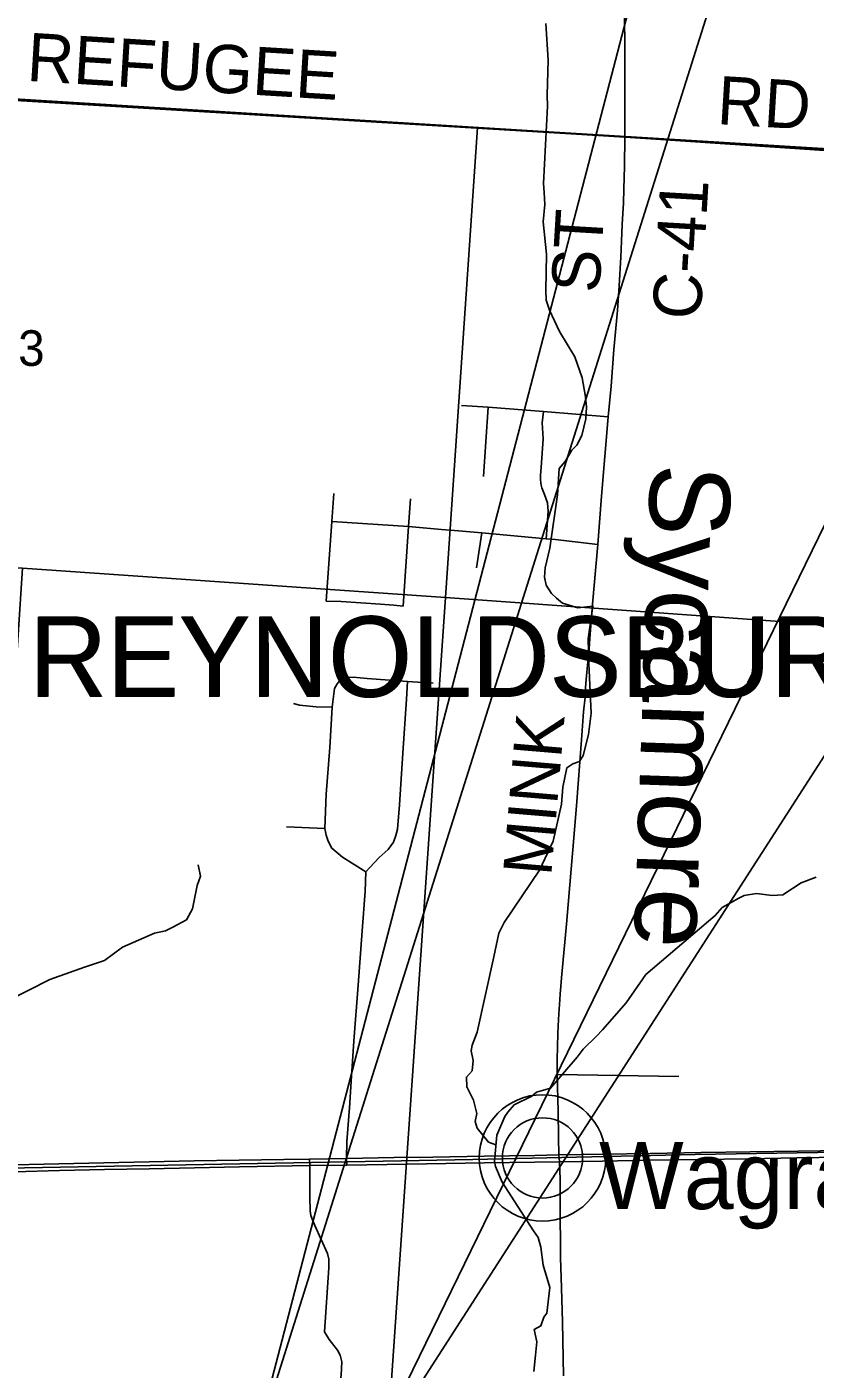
# Model space of a CAD drawing. Extents: x 0 to 34, y 0 to 22.
# Drawn here: x 2.718 to 3.646, y 16.964 to 18.544 of the extents above; entities that cross this region are included whole.
import ezdxf

# ---------------------------------------------------------------- set-up
doc = ezdxf.new("R2010")
doc.units = 0
for name, color, linetype in [('GM_X_City_Street', 7, 'Continuous'), ('GM_X_Corporation', 7, 'Continuous'), ('GM_X_Corporation_Text', 7, 'Continuous'), ('GM_X_County_Road', 7, 'Continuous'), ('GM_X_County_Road_Text', 7, 'Continuous'), ('GM_X_Minor_River', 7, 'Continuous'), ('GM_X_Minor_River_Text', 7, 'Continuous'), ('GM_X_Rail_Line', 7, 'Continuous'), ('GM_X_Section', 7, 'Continuous'), ('GM_X_Section_Text', 7, 'Continuous'), ('GM_X_Township_Road', 7, 'Continuous'), ('GM_X_Township_Road_Text', 7, 'Continuous'), ('GM_X_Unincorporated', 7, 'Continuous'), ('GM_X_Unincorporated_Location', 7, 'Continuous'), ('GM_X_Unincorporated_Text', 7, 'Continuous'), ('GM_X_US_Route', 7, 'Continuous'), ('SH_Text', 7, 'Continuous')]:
    doc.layers.add(name, color=color, linetype=linetype)

msp = doc.modelspace()

# ---------------------------------------------------------------- linework, layer by layer
at = {"layer": 'GM_X_City_Street'}
msp.add_lwpolyline([(8.3697, 20.9), (2.1, 20.9), (2.1, 18.8151), (2.1233, 18.8137), (2.129, 18.8133), (2.1078, 18.4924), (2.1111, 18.4924), (2.2415, 18.4869), (2.2482, 18.4853), (3.4177, 18.4149), (4.6284, 18.3336)], dxfattribs=at)
at = {"layer": 'GM_X_Corporation'}
for points in [[(6.4385, 20.9), (2.1, 20.9), (2.1, 18.4929), (2.1111, 18.4924), (2.2415, 18.4869), (2.5696, 18.468), (3.4218, 18.4152), (4.6285, 18.3373)], [(4.6285, 18.3373), (3.4218, 18.4152), (2.5696, 18.468), (2.2415, 18.4869), (2.1111, 18.4924), (2.1, 18.4929), (2.1, 15.9442), (2.2903, 15.9292), (2.5827, 15.9132), (2.6921, 15.9056), (2.7799, 15.8989), (2.8362, 15.8952), (3.3132, 15.8609), (3.9945, 15.8088)]]:
    msp.add_lwpolyline(points, dxfattribs=at)
at = {"layer": 'GM_X_County_Road'}
for points in [[(3.4075, 19.409), (3.4081, 19.3816), (3.409, 19.3382), (3.4098, 19.2932), (3.4107, 19.2269), (3.4112, 19.2096), (3.4118, 19.1857), (3.4122, 19.138), (3.413, 19.0859), (3.4136, 19.0691), (3.4144, 19.0397), (3.4155, 18.9809), (3.4164, 18.9378), (3.4171, 18.8919), (3.4175, 18.8583), (3.4184, 18.8084), (3.4193, 18.743), (3.4205, 18.6587), (3.421, 18.613), (3.4215, 18.5781), (3.4224, 18.5261), (3.4223, 18.4686), (3.4221, 18.4146)], [(3.4221, 18.4146), (3.4218, 18.3802), (3.4209, 18.3532), (3.4205, 18.3371), (3.4191, 18.3117), (3.4184, 18.2921), (3.4175, 18.2734), (3.4156, 18.2396), (3.4136, 18.2104), (3.4095, 18.1646), (3.4062, 18.1213), (3.4027, 18.0854), (3.3949, 17.9919), (3.3904, 17.935), (3.3844, 17.8647), (3.381, 17.8244), (3.3797, 17.8067), (3.3784, 17.7929), (3.3773, 17.7805), (3.376, 17.7666), (3.3754, 17.7553), (3.3738, 17.7381), (3.3713, 17.705), (3.3693, 17.6792), (3.3675, 17.6534), (3.3659, 17.6326), (3.3622, 17.5898), (3.3575, 17.5344), (3.3535, 17.4882), (3.3478, 17.4248), (3.3469, 17.4148), (3.3463, 17.4059), (3.3457, 17.3989), (3.3446, 17.3826), (3.3438, 17.3685), (3.3434, 17.3589), (3.343, 17.344), (3.3428, 17.3284), (3.3428, 17.3185), (3.3428, 17.3112), (3.3437, 17.2678), (3.344, 17.2369), (3.3446, 17.2166), (3.3453, 17.2083)], [(3.3453, 17.2083), (3.3463, 17.1876), (3.3461, 17.1598), (3.3465, 17.0957), (3.3479, 17.0598), (3.349, 17.0196), (3.3501, 16.9565)]]:
    msp.add_lwpolyline(points, dxfattribs=at)
at = {"layer": 'GM_X_Minor_River'}
for points in [[(3.2706, 17.2284), (3.2619, 17.2313), (3.2483, 17.248), (3.246, 17.2556), (3.2479, 17.2651), (3.2442, 17.2807), (3.2363, 17.2966), (3.2359, 17.308), (3.2424, 17.3156), (3.2439, 17.3274), (3.2413, 17.3388), (3.2424, 17.3456), (3.2485, 17.3611), (3.268, 17.4495), (3.2741, 17.4776), (3.2802, 17.4901), (3.322, 17.5515), (3.3349, 17.5792), (3.338, 17.5856), (3.3479, 17.6293), (3.3491, 17.6494), (3.354, 17.6722), (3.3612, 17.6767), (3.3688, 17.6797), (3.3734, 17.6865), (3.3795, 17.7112), (3.3826, 17.7366), (3.38, 17.7951), (3.3793, 17.8239), (3.3847, 17.8626), (3.3669, 17.8604), (3.3488, 17.8661), (3.3419, 17.8718), (3.3359, 17.8772), (3.3295, 17.887), (3.3276, 17.8965), (3.3284, 17.9075), (3.3341, 17.9307), (3.343, 17.9933), (3.3449, 18.0244), (3.3521, 18.0327), (3.3597, 18.046), (3.3658, 18.0521), (3.3715, 18.0634), (3.3765, 18.0828), (3.3772, 18.0965), (3.3761, 18.109), (3.3743, 18.1177), (3.372, 18.1314), (3.3634, 18.1561), (3.3452, 18.1857), (3.3335, 18.2108), (3.3298, 18.2226), (3.3291, 18.234), (3.3299, 18.2769), (3.3262, 18.3148), (3.3281, 18.3353), (3.3274, 18.3494), (3.3267, 18.36), (3.3314, 18.4511), (3.331, 18.464), (3.3319, 18.5053), (3.3293, 18.5482)], [(2.6703, 17.3848), (2.7454, 17.423), (2.7863, 17.4373), (2.8098, 17.4452), (2.831, 17.4608), (2.8686, 17.4774), (2.8818, 17.4804), (2.8902, 17.4845), (2.9065, 17.4932), (2.9133, 17.5061), (2.919, 17.5334), (2.9228, 17.5444), (2.9202, 17.5581)], [(3.3151, 16.9616), (3.317, 16.9806), (3.3186, 16.9962), (3.3156, 17.011), (3.3235, 17.0152), (3.327, 17.0254), (3.3304, 17.0303), (3.3339, 17.0603), (3.326, 17.0865), (3.3234, 17.1078), (3.3204, 17.1192), (3.3147, 17.1272), (3.2777, 17.1842), (3.2702, 17.2028), (3.2687, 17.2089), (3.2717, 17.2396), (3.2809, 17.2616), (3.2847, 17.2669), (3.2919, 17.2753), (3.3127, 17.2855), (3.3184, 17.2904), (3.3347, 17.2949), (3.3662, 17.3313), (3.3731, 17.3411), (3.389, 17.3563), (3.3958, 17.3635), (3.4239, 17.3953), (3.4471, 17.429), (3.5286, 17.4983), (3.537, 17.5078), (3.5563, 17.5187), (3.5628, 17.5218), (3.5772, 17.524), (3.5957, 17.5217), (3.6082, 17.5224), (3.6298, 17.5368), (3.6473, 17.5432)]]:
    msp.add_lwpolyline(points, dxfattribs=at)
at = {"layer": 'GM_X_Rail_Line'}
msp.add_lwpolyline([(2.1, 17.1885), (2.293, 17.1932), (3.2433, 17.211), (3.5049, 17.2168), (5.1641, 17.2441), (5.3961, 17.2441), (6.3843, 17.2591), (6.7484, 17.272), (7.243, 17.2836), (8.0477, 17.3015), (8.4974, 17.3184), (8.9, 17.3324)], dxfattribs=at)
at = {"layer": 'GM_X_Section'}
for points in [[(2.2377, 18.4824), (2.6283, 18.4625), (3.1458, 18.432), (3.2487, 18.4259), (3.2112, 17.8728), (2.7132, 17.9071), (2.1995, 17.9442)], [(3.2487, 18.4259), (3.6748, 18.4), (4.2612, 18.3613), (4.2214, 17.7996), (3.7302, 17.8352), (3.2112, 17.8728)], [(2.7132, 17.9071), (3.2112, 17.8728), (3.1425, 16.8774), (2.648, 16.9108)], [(3.2112, 17.8728), (3.7302, 17.8352), (3.6598, 16.8406), (3.1425, 16.8774)]]:
    msp.add_lwpolyline(points, close=True, dxfattribs=at)
at = {"layer": 'GM_X_Township_Road'}
for p, q in [((3.2561, 18.0152), (3.2613, 18.0968)), ((3.2478, 17.9075), (3.254, 17.9489)), ((3.0242, 17.6025), (3.069, 17.6005)), ((3.3428, 17.3112), (3.4857, 17.3088))]:
    msp.add_line(p, q, dxfattribs=at)
for points in [[(3.4221, 18.4146), (2.5698, 18.4675), (2.2417, 18.4863)], [(5.2116, 18.2984), (4.6288, 18.3368), (3.4221, 18.4146)], [(3.23, 18.0985), (3.2613, 18.0968), (3.3265, 18.0916), (3.4027, 18.0854)], [(3.3297, 17.9416), (3.3321, 17.9741), (3.3312, 17.984), (3.3277, 17.994), (3.3247, 18.0016), (3.3237, 18.0048), (3.3233, 18.0076), (3.3229, 18.0116), (3.323, 18.0167), (3.3237, 18.0255), (3.326, 18.0594), (3.3248, 18.0781), (3.3265, 18.0916)], [(3.0707, 17.8683), (3.0774, 17.9621), (3.0798, 17.9951)], [(3.1615, 17.8624), (3.1678, 17.9561), (3.17, 17.9888)], [(3.0774, 17.9621), (3.1678, 17.9561), (3.2064, 17.9526), (3.2219, 17.9514)], [(3.2219, 17.9514), (3.2263, 17.9511), (3.254, 17.9489), (3.3297, 17.9416), (3.3401, 17.9409), (3.3904, 17.935)], [(3.0707, 17.8683), (3.0882, 17.8679), (3.1346, 17.8646), (3.1502, 17.8635), (3.1615, 17.8624)], [(3.1173, 17.5497), (3.0898, 17.5668), (3.0776, 17.5774), (3.0729, 17.5859), (3.0706, 17.5929), (3.069, 17.6005), (3.0709, 17.6411), (3.0749, 17.696), (3.0779, 17.7435), (3.0806, 17.7656), (3.0835, 17.7711), (3.0878, 17.7756), (3.093, 17.778), (3.1024, 17.7788), (3.119, 17.7772)], [(3.119, 17.7772), (3.1664, 17.7738), (3.1966, 17.7716)], [(3.0949, 17.2044), (3.0947, 17.2123), (3.0952, 17.2322), (3.0982, 17.272), (3.1007, 17.3091), (3.1034, 17.3502), (3.1084, 17.4163), (3.1131, 17.4801), (3.1165, 17.5266), (3.1173, 17.5497), (3.1222, 17.5548), (3.1331, 17.5665), (3.1436, 17.5761), (3.1499, 17.5847), (3.1528, 17.5923), (3.1547, 17.6), (3.1569, 17.6287), (3.1611, 17.6894), (3.1654, 17.753), (3.1664, 17.7738)], [(3.0323, 17.7478), (3.0394, 17.746), (3.0588, 17.7439), (3.0779, 17.7435)], [(3.0513, 17.2116), (3.0514, 17.2038), (3.0516, 17.1668), (3.052, 17.1507), (3.0528, 17.1452), (3.0546, 17.14), (3.0575, 17.1333), (3.0725, 17.1005), (3.074, 17.0936), (3.0738, 17.0835), (3.0687, 17.008), (3.0744, 16.9992)], [(3.0855, 16.9316), (3.0885, 16.9576), (3.0891, 16.973), (3.0874, 16.9807), (3.0839, 16.9866), (3.0744, 16.9992)]]:
    msp.add_lwpolyline(points, dxfattribs=at)
at = {"layer": 'GM_X_Unincorporated'}
for radius in [0.0744, 0.0472]:
    msp.add_circle((3.3254, 17.2129), radius, dxfattribs=at)
at = {"layer": 'GM_X_Unincorporated_Location'}
msp.add_line((3.3254, 17.2129), (3.3254, 17.2129), dxfattribs=at)
at = {"layer": 'GM_X_US_Route'}
for points in [[(2.7041, 17.2047), (2.7562, 17.2059), (2.8091, 17.2071), (2.8624, 17.2082), (2.9155, 17.2093), (2.9682, 17.2103), (3.0208, 17.2111), (3.0513, 17.2116), (3.0947, 17.2123), (3.1507, 17.2132), (3.1964, 17.2139), (3.2567, 17.2149), (3.3163, 17.2159), (3.3446, 17.2166), (3.3971, 17.2173), (3.4519, 17.2182), (3.512, 17.2192), (3.5697, 17.22), (3.6263, 17.221), (3.6789, 17.2218)], [(2.7041, 17.1966), (2.757, 17.1979), (2.8097, 17.1992), (2.8626, 17.2002), (2.9157, 17.2014), (2.9688, 17.2023), (3.0514, 17.2038), (3.0949, 17.2044), (3.1662, 17.2055), (3.2569, 17.207), (3.3165, 17.2078), (3.3453, 17.2083), (3.3955, 17.2091), (3.4503, 17.2101), (3.5104, 17.2111), (3.568, 17.212), (3.6247, 17.2129), (3.6773, 17.2137)]]:
    msp.add_lwpolyline(points, dxfattribs=at)
at = {"layer": 'SH_Text'}
for points in [[(2.98, 16.8495), (3.6186, 18.8742), (3.6186, 19.301)], [(3.1124, 16.8393), (3.9683, 18.1701), (3.9683, 18.5968)]]:
    msp.add_lwpolyline(points, close=True, dxfattribs=at)

# ---------------------------------------------------------------- texts
at = {"layer": 'GM_X_Corporation_Text'}
for p in [(2.7208, 17.7555), (2.722, 17.7558)]:
    msp.add_text('REYNOLDSBURG', height=0.094697, rotation=0, dxfattribs=at).set_placement(p)
at = {"layer": 'GM_X_County_Road_Text'}
for s, rotation, p in [('C-41', 86.6637, (3.5113, 18.1988)), ('ST', 86.604, (3.3922, 18.2305)), ('MINK', 85.1744, (3.3355, 17.5438))]:
    msp.add_text(s, height=0.05682, rotation=rotation, dxfattribs=at).set_placement(p)
at = {"layer": 'GM_X_Minor_River_Text'}
msp.add_text('Sycamore', height=0.09469, rotation=268.0002, dxfattribs=at).set_placement((3.4528, 18.0309))
at = {"layer": 'GM_X_Section_Text'}
msp.add_text('3', height=0.0419, rotation=0, dxfattribs=at).set_placement((2.7082, 18.1453))
at = {"layer": 'GM_X_Township_Road_Text'}
for s, rotation, p in [('REFUGEE', 356.4805, (2.7175, 18.4809)), ('RD', 356.5467, (3.5299, 18.43))]:
    msp.add_text(s, height=0.05682, rotation=rotation, dxfattribs=at).set_placement(p)
at = {"layer": 'GM_X_Unincorporated_Text'}
msp.add_text('Wagram', height=0.07898, rotation=0, dxfattribs=at).set_placement((3.3919, 17.1527))

doc.saveas('drawing.dxf')
